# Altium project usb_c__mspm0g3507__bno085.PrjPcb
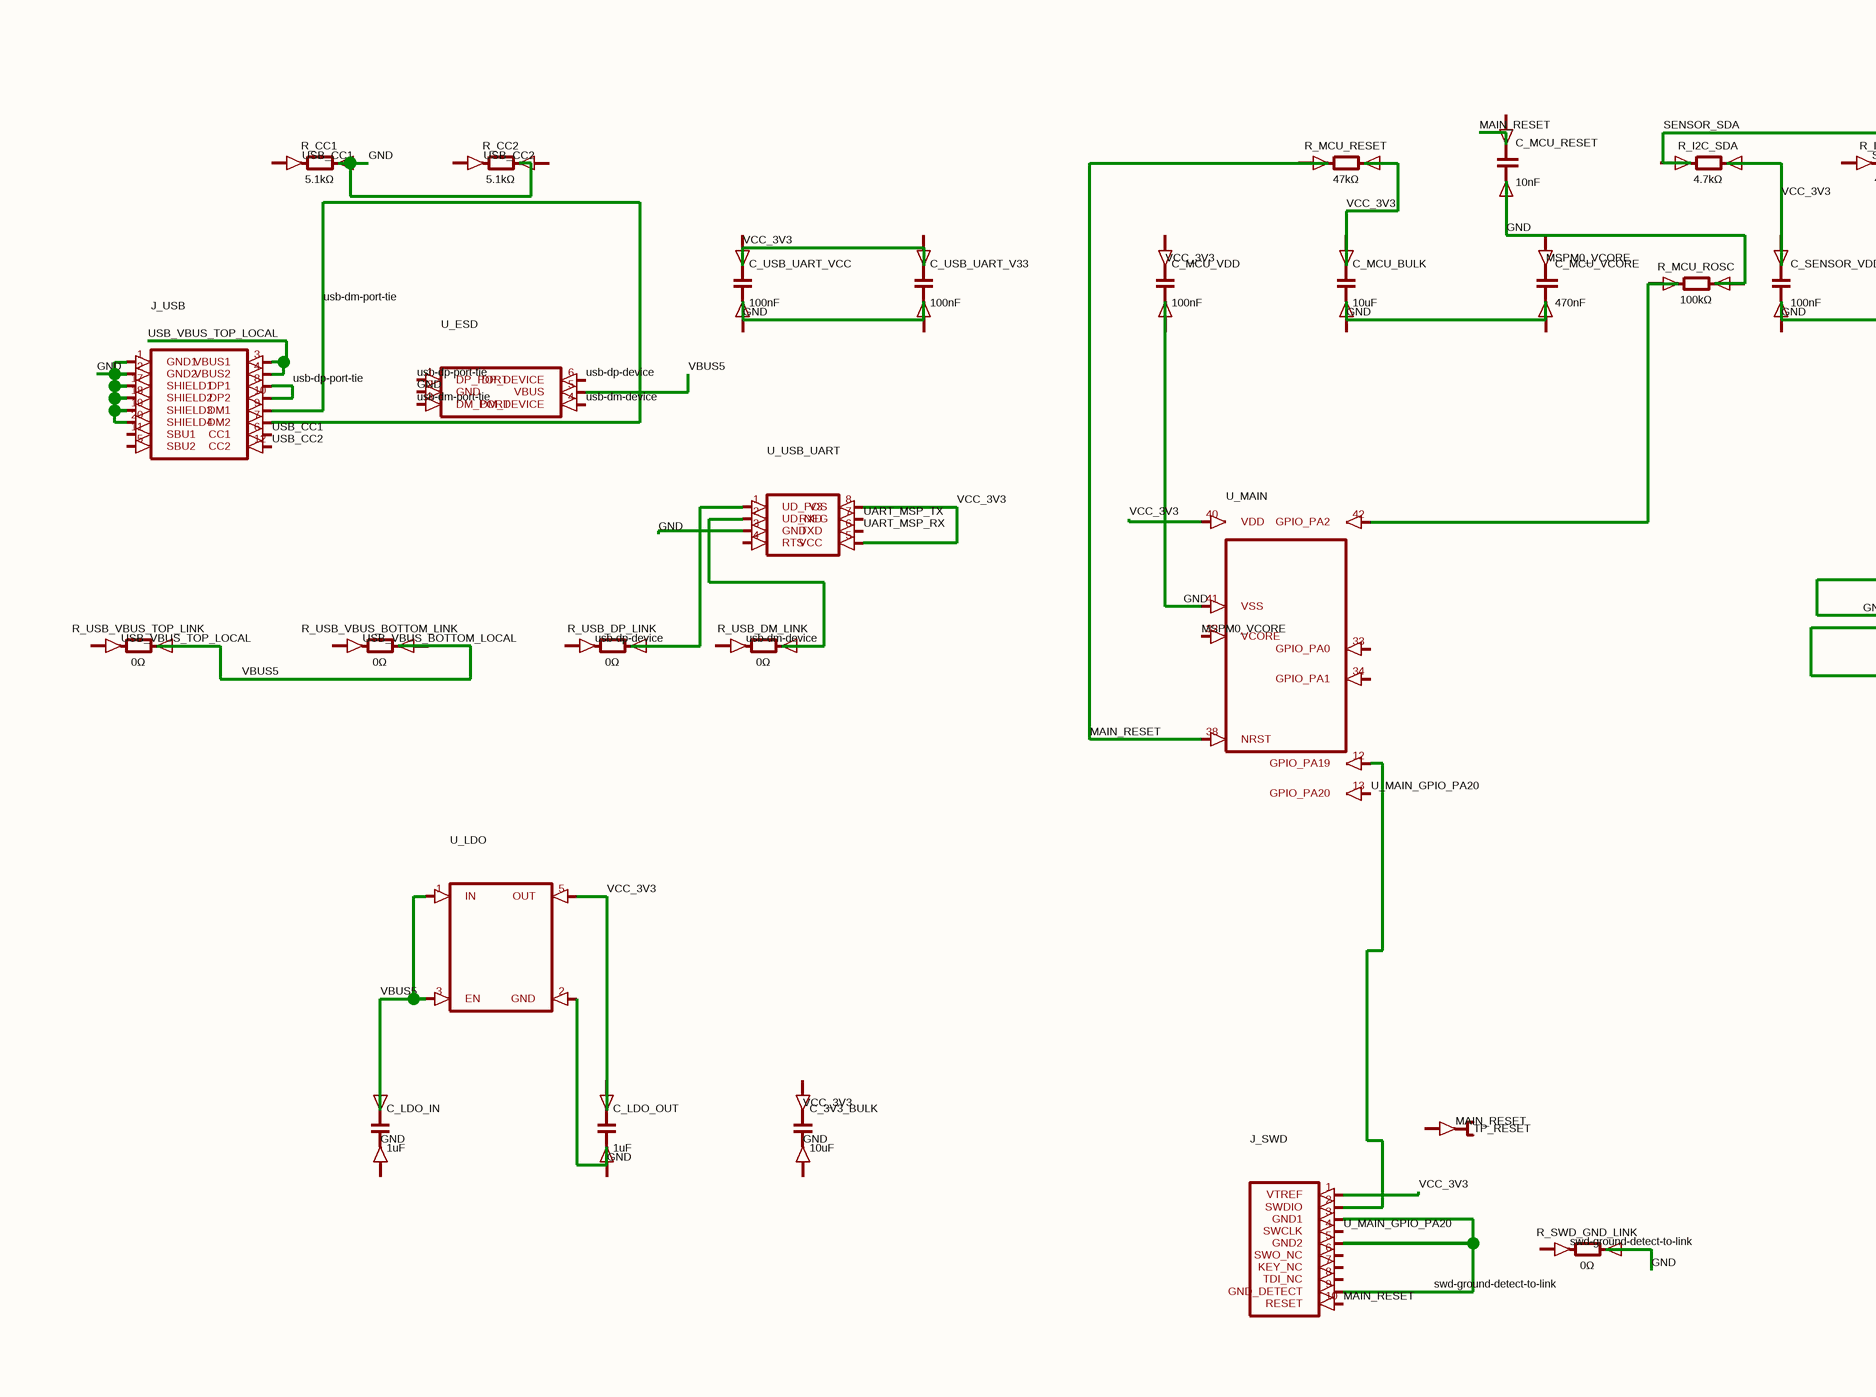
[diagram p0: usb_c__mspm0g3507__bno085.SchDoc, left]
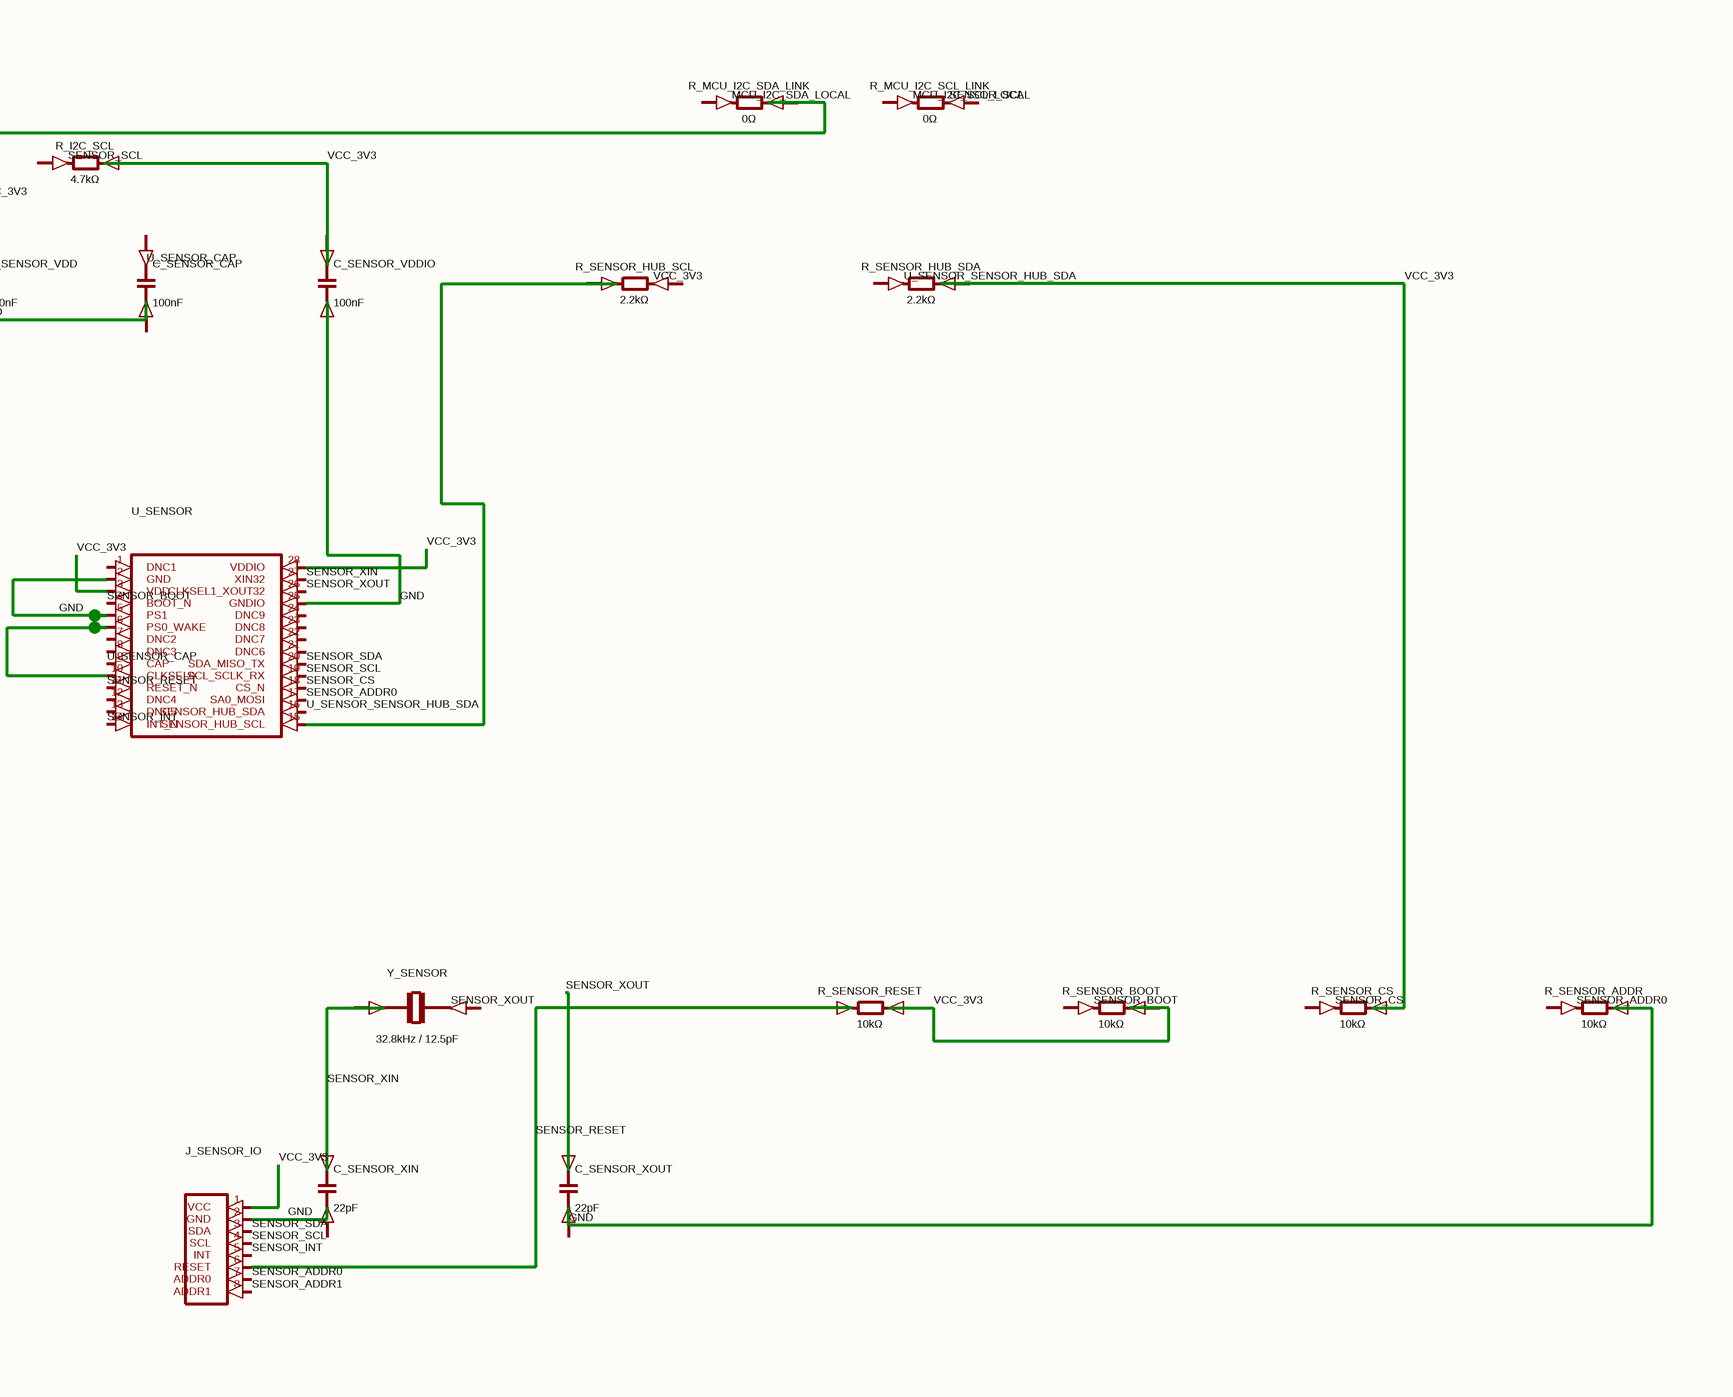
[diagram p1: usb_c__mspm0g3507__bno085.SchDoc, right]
1 sheet, 43 parts. Net scope: global (net labels, ports and power ports of the same name join across sheets).
Board file: usb_c__mspm0g3507__bno085.PcbDoc

## Sheet usb_c__mspm0g3507__bno085.SchDoc
size 337 x 151 mm

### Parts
C_3V3_BULK  10uF
C_LDO_IN  1uF
C_LDO_OUT  1uF
C_MCU_BULK  10uF
C_MCU_RESET  10nF
C_MCU_VCORE  470nF
C_MCU_VDD  100nF
C_SENSOR_CAP  100nF
C_SENSOR_VDD  100nF
C_SENSOR_VDDIO  100nF
C_SENSOR_XIN  22pF
C_SENSOR_XOUT  22pF
C_USB_UART_V33  100nF
C_USB_UART_VCC  100nF
J_SENSOR_IO  (no value)
J_SWD  (no value)
J_USB  (no value)
R_CC1  5.1kΩ
R_CC2  5.1kΩ
R_I2C_SCL  4.7kΩ
R_I2C_SDA  4.7kΩ
R_MCU_I2C_SCL_LINK  0Ω
R_MCU_I2C_SDA_LINK  0Ω
R_MCU_RESET  47kΩ
R_MCU_ROSC  100kΩ
R_SENSOR_ADDR  10kΩ
R_SENSOR_BOOT  10kΩ
R_SENSOR_CS  10kΩ
R_SENSOR_HUB_SCL  2.2kΩ
R_SENSOR_HUB_SDA  2.2kΩ
R_SENSOR_RESET  10kΩ
R_SWD_GND_LINK  0Ω
R_USB_DM_LINK  0Ω
R_USB_DP_LINK  0Ω
R_USB_VBUS_BOTTOM_LINK  0Ω
R_USB_VBUS_TOP_LINK  0Ω
TP_RESET  (no value)
U_ESD  (no value)
U_LDO  (no value)
U_MAIN  (no value)
U_SENSOR  (no value)
U_USB_UART  (no value)
Y_SENSOR  32.8kHz / 12.5pF

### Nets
GND: C_LDO_OUT.1(anode) C_MCU_BULK.1(anode) C_MCU_RESET.2(cathode) C_MCU_VCORE.1(anode) C_MCU_VDD.2(cathode) C_SENSOR_VDD.1(anode) C_SENSOR_VDDIO.1(anode) C_SENSOR_VDDIO.2(cathode) J_SENSOR_IO.1(VCC) J_SENSOR_IO.2(GND) J_SWD.1(VTREF) J_USB.1(GND1) J_USB.2(GND2) J_USB.17(SHIELD1) J_USB.18(SHIELD2) J_USB.19(SHIELD3) J_USB.20(SHIELD4) R_CC1.2(cathode) R_I2C_SCL.2(cathode) R_I2C_SDA.2(cathode) R_MCU_RESET.2(cathode) R_MCU_ROSC.2(cathode) R_SENSOR_ADDR.2(cathode) R_SENSOR_BOOT.2(cathode) R_SENSOR_CS.2(cathode) R_SENSOR_HUB_SDA.2(cathode) R_SENSOR_RESET.2(cathode) R_SWD_GND_LINK.2(cathode) R_USB_DM_LINK.2(cathode) R_USB_DP_LINK.2(cathode) U_ESD.2(GND) U_LDO.2(GND) U_LDO.5(OUT) U_MAIN.40(VDD) U_MAIN.41(VSS) U_SENSOR.2(GND) U_SENSOR.3(VDD) U_SENSOR.5(PS1) U_SENSOR.6(PS0_WAKE) U_SENSOR.10(CLKSEL0) U_SENSOR.25(GNDIO) U_SENSOR.28(VDDIO) U_USB_UART.1(UD_POS) U_USB_UART.2(UD_NEG) U_USB_UART.3(GND) U_USB_UART.5(VCC) U_USB_UART.8(V3)  [also labelled VCC_3V3]
MAIN_RESET: J_SWD.10(RESET) R_MCU_RESET.1(anode) U_MAIN.38(NRST)
MSPM0_VCORE: U_MAIN.32(VCORE)
SENSOR_ADDR0: J_SENSOR_IO.7(ADDR0) U_SENSOR.17(SA0_MOSI)
SENSOR_ADDR1: J_SENSOR_IO.8(ADDR1)
SENSOR_BOOT: U_SENSOR.4(BOOT_N)
SENSOR_CS: U_SENSOR.18(CS_N)
SENSOR_INT: J_SENSOR_IO.5(INT) U_SENSOR.14(INT_N)
SENSOR_RESET: J_SENSOR_IO.6(RESET) R_SENSOR_RESET.1(anode) U_SENSOR.11(RESET_N)
SENSOR_SCL: J_SENSOR_IO.4(SCL) U_SENSOR.19(SCL_SCLK_RX)
SENSOR_SDA: J_SENSOR_IO.3(SDA) R_MCU_I2C_SDA_LINK.2(cathode) U_SENSOR.20(SDA_MISO_TX)
SENSOR_XIN: C_SENSOR_XIN.1(anode) U_SENSOR.27(XIN32) Y_SENSOR.1(pos)
SENSOR_XOUT: C_SENSOR_XOUT.1(anode) U_SENSOR.26(CLKSEL1_XOUT32)
swd-ground-detect-to-link: J_SWD.3(GND1) J_SWD.5(GND2) J_SWD.9(GND_DETECT)
U_MAIN_GPIO_PA20: J_SWD.4(SWCLK) U_MAIN.13(GPIO_PA20)
U_SENSOR_CAP: U_SENSOR.9(CAP)
U_SENSOR_SENSOR_HUB_SDA: U_SENSOR.16(SENSOR_HUB_SDA)
UART_MSP_RX: U_USB_UART.6(TXD)
UART_MSP_TX: U_USB_UART.7(RXD)
usb-dm-device: U_ESD.4(DM_DEVICE)
usb-dm-port-tie: C_LDO_IN.1(anode) J_USB.7(DM2) J_USB.9(DM1) R_USB_VBUS_BOTTOM_LINK.2(cathode) R_USB_VBUS_TOP_LINK.2(cathode) U_ESD.3(DM_PORT) U_ESD.5(VBUS) U_LDO.1(IN) U_LDO.3(EN)  [also labelled VBUS5]
usb-dp-device: U_ESD.6(DP_DEVICE)
usb-dp-port-tie: J_USB.8(DP1) J_USB.10(DP2) U_ESD.1(DP_PORT)
USB_CC1: J_USB.6(CC1)
USB_CC2: J_USB.12(CC2)
USB_VBUS_TOP_LOCAL: J_USB.3(VBUS1) J_USB.4(VBUS2)
NetJ_SWD_2: J_SWD.2(SWDIO) U_MAIN.12(GPIO_PA19)
NetR_MCU_ROSC_1: R_MCU_ROSC.1(anode) U_MAIN.42(GPIO_PA2)
NetR_SENSOR_HUB_SCL_1: R_SENSOR_HUB_SCL.1(anode) U_SENSOR.15(SENSOR_HUB_SCL)

Not connected (* = marked no-connect by the designer): C_3V3_BULK 1(anode) 2(cathode); C_LDO_IN 2(cathode); C_LDO_OUT 2(cathode); C_MCU_BULK 2(cathode); C_MCU_RESET 1(anode); C_MCU_VCORE 2(cathode); C_MCU_VDD 1(anode); C_SENSOR_CAP 1(anode) 2(cathode); C_SENSOR_VDD 2(cathode); C_SENSOR_XIN 2(cathode); C_SENSOR_XOUT 2(cathode); C_USB_UART_V33 1(anode) 2(cathode); C_USB_UART_VCC 1(anode) 2(cathode); J_SWD 6(SWO_NC) 7(KEY_NC) 8(TDI_NC); J_USB 5(SBU2) 11(SBU1); R_CC1 1(anode); R_CC2 1(anode) 2(cathode); R_I2C_SCL 1(anode); R_I2C_SDA 1(anode); R_MCU_I2C_SCL_LINK 1(anode) 2(cathode); R_MCU_I2C_SDA_LINK 1(anode); R_SENSOR_ADDR 1(anode); R_SENSOR_BOOT 1(anode); R_SENSOR_CS 1(anode); R_SENSOR_HUB_SCL 2(cathode); R_SENSOR_HUB_SDA 1(anode); R_SWD_GND_LINK 1(anode); R_USB_DM_LINK 1(anode); R_USB_DP_LINK 1(anode); R_USB_VBUS_BOTTOM_LINK 1(anode); R_USB_VBUS_TOP_LINK 1(anode); TP_RESET 1(pin1); U_MAIN 33(GPIO_PA0) 34(GPIO_PA1); U_SENSOR 1(DNC1) 7(DNC2) 8(DNC3) 12(DNC4) 13(DNC5) 21(DNC6) 22(DNC7) 23(DNC8) 24(DNC9); U_USB_UART 4(RTS); Y_SENSOR 2(neg)

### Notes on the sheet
- Labels drawn without touching a wire or pin: GND, MAIN_RESET, MCU_I2C_SCL_LOCAL, MCU_I2C_SDA_LOCAL, MSPM0_VCORE, SENSOR_ADDR0, SENSOR_BOOT, SENSOR_CS, SENSOR_SCL, SENSOR_XOUT, swd-ground-detect-to-link, U_SENSOR_CAP, U_SENSOR_SENSOR_HUB_SDA, usb-dm-device, usb-dp-device, USB_CC1, USB_CC2, USB_VBUS_BOTTOM_LOCAL, USB_VBUS_TOP_LOCAL, VCC_3V3

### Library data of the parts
C_3V3_BULK C_LDO_IN C_LDO_OUT C_MCU_BULK C_MCU_RESET C_MCU_VCORE C_MCU_VDD C_SENSOR_CAP C_SENSOR_VDD C_SENSOR_VDDIO C_SENSOR_XIN C_SENSOR_XOUT C_USB_UART_V33 C_USB_UART_VCC = capacitor_down
J_SENSOR_IO = J_SENSOR_IO
J_SWD = J_SWD
J_USB = J_USB
R_CC1 R_CC2 R_I2C_SCL R_I2C_SDA R_MCU_I2C_SCL_LINK R_MCU_I2C_SDA_LINK R_MCU_RESET R_MCU_ROSC R_SENSOR_ADDR R_SENSOR_BOOT R_SENSOR_CS R_SENSOR_HUB_SCL R_SENSOR_HUB_SDA R_SENSOR_RESET R_SWD_GND_LINK R_USB_DM_LINK R_USB_DP_LINK R_USB_VBUS_BOTTOM_LINK R_USB_VBUS_TOP_LINK = boxresistor_right
TP_RESET = testpoint_right
U_ESD = U_ESD
U_LDO = U_LDO
U_MAIN = U_MAIN
U_SENSOR = U_SENSOR
U_USB_UART = U_USB_UART
Y_SENSOR = crystal_right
